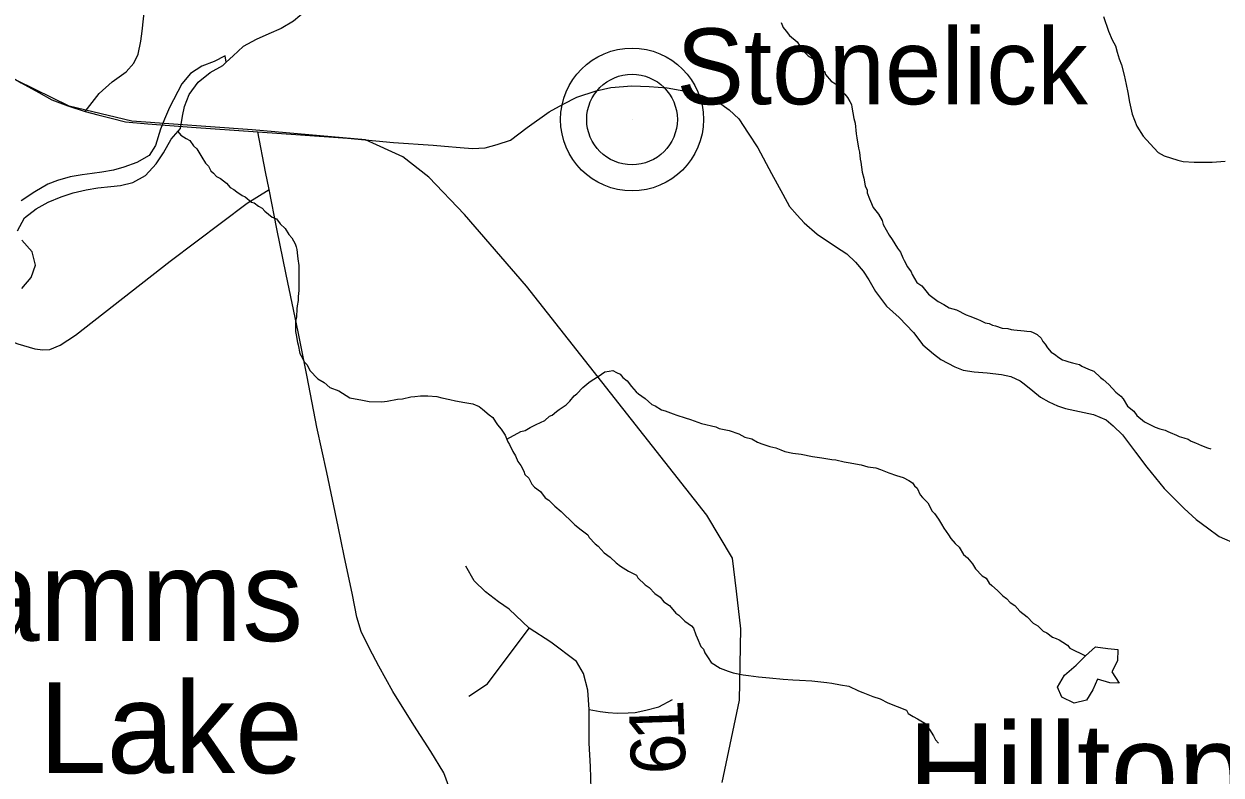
# Model space of a CAD drawing. Extents: x 0 to 34, y 0 to 22.
# Drawn here: x 4.243 to 5.489, y 19.569 to 20.352 of the extents above; entities that cross this region are included whole.
import ezdxf

# ---------------------------------------------------------------- set-up
doc = ezdxf.new("R2010")
doc.units = 0
for name, color, linetype in [('GM_X_County_Road', 7, 'Continuous'), ('GM_X_Major_River', 7, 'Continuous'), ('GM_X_Minor_Lake', 7, 'Continuous'), ('GM_X_Minor_Lake_Text', 7, 'Continuous'), ('GM_X_Minor_River', 7, 'Continuous'), ('GM_X_Rail_Line', 7, 'Continuous'), ('GM_X_State_Route', 7, 'Continuous'), ('GM_X_Township_Road', 7, 'Continuous'), ('GM_X_Township_Road_Text', 7, 'Continuous'), ('GM_X_Unincorporated', 7, 'Continuous'), ('GM_X_Unincorporated_Location', 7, 'Continuous'), ('GM_X_Unincorporated_Text', 7, 'Continuous'), ('GM_X_US_Route', 7, 'Continuous')]:
    doc.layers.add(name, color=color, linetype=linetype)

msp = doc.modelspace()

# ---------------------------------------------------------------- linework, layer by layer
at = {"layer": 'GM_X_County_Road'}
for points in [[(4.3064, 20.2608), (4.321, 20.2794), (4.3346, 20.2916), (4.3491, 20.3021), (4.3573, 20.3109), (4.3617, 20.3202), (4.3643, 20.3339), (4.3659, 20.3445), (4.3681, 20.367)], [(3.9526, 20.0204), (3.9769, 20.0241), (4.0253, 20.0318), (4.079, 20.0398), (4.14, 20.0481), (4.1548, 20.0481), (4.1672, 20.0451), (4.1845, 20.0388), (4.2363, 20.0188), (4.254, 20.0134), (4.2623, 20.0125), (4.2697, 20.0128), (4.2806, 20.0172), (4.2963, 20.0276), (4.3951, 20.1048), (4.4752, 20.1652), (4.4982, 20.1794)]]:
    msp.add_lwpolyline(points, dxfattribs=at)
at = {"layer": 'GM_X_Major_River'}
for points in [[(4.5679, 20.3824), (4.5488, 20.3747), (4.5365, 20.3658), (4.5234, 20.3546), (4.5104, 20.3472), (4.4977, 20.3417), (4.4847, 20.3355), (4.4709, 20.3285), (4.4605, 20.3188), (4.4533, 20.312)], [(4.4533, 20.312), (4.4522, 20.3185), (4.4407, 20.3126), (4.4281, 20.3079), (4.4162, 20.3001), (4.4073, 20.2896), (4.3943, 20.2647), (4.3892, 20.2527), (4.3848, 20.2421), (4.3796, 20.2251), (4.373, 20.2149), (4.3603, 20.2075), (4.3466, 20.2028), (4.3359, 20.1996), (4.3237, 20.1975), (4.3138, 20.1961), (4.3035, 20.1948), (4.291, 20.1927), (4.2776, 20.1887), (4.2677, 20.1851), (4.2539, 20.177), (4.24, 20.1677)], [(4.2361, 20.1362), (4.2432, 20.1498), (4.2555, 20.1591), (4.2681, 20.1661), (4.2815, 20.1719), (4.2941, 20.1759), (4.3075, 20.1791), (4.3196, 20.1812), (4.3333, 20.1825), (4.3432, 20.1835), (4.3562, 20.1867), (4.3692, 20.1941), (4.3804, 20.206), (4.3882, 20.2177), (4.3961, 20.232), (4.4057, 20.2429), (4.4078, 20.2558), (4.4099, 20.266), (4.4147, 20.2785), (4.424, 20.2912), (4.4367, 20.3013), (4.4497, 20.3087), (4.4533, 20.312)], [(4.2404, 20.0761), (4.2501, 20.0877), (4.2549, 20.1005), (4.2513, 20.1143), (4.2405, 20.1266)]]:
    msp.add_lwpolyline(points, dxfattribs=at)
at = {"layer": 'GM_X_Minor_Lake'}
msp.add_lwpolyline([(5.3481, 19.6936), (5.3585, 19.7029), (5.3714, 19.7012), (5.3817, 19.7002), (5.3815, 19.6884), (5.3756, 19.6771), (5.383, 19.6652), (5.3735, 19.6654), (5.3606, 19.6694), (5.3558, 19.6581), (5.3492, 19.6476), (5.3362, 19.6444), (5.3234, 19.6507), (5.319, 19.661), (5.3261, 19.6734), (5.3384, 19.6839)], dxfattribs=at)
at = {"layer": 'GM_X_Minor_River'}
for points in [[(5.3669, 20.3595), (5.372, 20.3442), (5.376, 20.3354), (5.3794, 20.3292), (5.3811, 20.3224), (5.3833, 20.3155), (5.3855, 20.3093), (5.3883, 20.2986), (5.3905, 20.2887), (5.3922, 20.2803), (5.3939, 20.2704), (5.3968, 20.2578), (5.4015, 20.2452), (5.4082, 20.2348), (5.4153, 20.227), (5.4239, 20.2178), (5.4299, 20.2146), (5.4442, 20.2098), (5.4499, 20.2086), (5.4613, 20.208), (5.4735, 20.2078), (5.48, 20.208), (5.4937, 20.2089)], [(5.0312, 20.3534), (5.0333, 20.3482), (5.0363, 20.3444), (5.04, 20.3398), (5.0479, 20.3332), (5.0509, 20.3285), (5.0535, 20.3247), (5.0594, 20.3185), (5.0651, 20.315), (5.0658, 20.3123), (5.0714, 20.3061), (5.0767, 20.3018), (5.0774, 20.2992), (5.0833, 20.2922), (5.0878, 20.2895), (5.0923, 20.2837), (5.0975, 20.2787), (5.1002, 20.2752), (5.1027, 20.271), (5.1046, 20.2679), (5.1049, 20.2652), (5.107, 20.2534), (5.1081, 20.2484), (5.1094, 20.2374), (5.1101, 20.2332), (5.1118, 20.2225), (5.1129, 20.2183), (5.1135, 20.211), (5.1142, 20.208), (5.1156, 20.1973), (5.1174, 20.1912), (5.1187, 20.1832), (5.1206, 20.1786), (5.1209, 20.1759), (5.1231, 20.1698), (5.1242, 20.1671), (5.1271, 20.1606), (5.1327, 20.1537), (5.1364, 20.1471), (5.1375, 20.1429), (5.1437, 20.1318), (5.1467, 20.1272), (5.1522, 20.1183), (5.1556, 20.1141), (5.1578, 20.1083), (5.1593, 20.1053), (5.1626, 20.0987), (5.1667, 20.0937), (5.1677, 20.0907), (5.1726, 20.0826), (5.1778, 20.0791), (5.1845, 20.0702), (5.1879, 20.0679), (5.1947, 20.0628), (5.2007, 20.0596), (5.2063, 20.0561), (5.2139, 20.0541), (5.2237, 20.049), (5.2278, 20.0474), (5.2358, 20.0442), (5.2388, 20.043), (5.2437, 20.0406), (5.2479, 20.0398), (5.2513, 20.0382), (5.2543, 20.0374), (5.2615, 20.035), (5.2672, 20.0345), (5.2706, 20.0337), (5.2736, 20.0333), (5.2842, 20.0323), (5.2869, 20.0319), (5.2911, 20.0314), (5.2937, 20.0306), (5.2979, 20.0283), (5.302, 20.0244), (5.3038, 20.0209), (5.306, 20.0182), (5.3086, 20.0144), (5.3124, 20.0101), (5.3158, 20.0078), (5.3203, 20.0043), (5.324, 20.0019), (5.3267, 20.0011), (5.3308, 19.9999), (5.3346, 19.9987), (5.3388, 19.9979), (5.3418, 19.9971), (5.3444, 19.9955), (5.3512, 19.9923), (5.3569, 19.99), (5.3636, 19.9834), (5.3666, 19.9814), (5.3723, 19.9764), (5.3797, 19.9683), (5.385, 19.964), (5.3872, 19.9613), (5.392, 19.9536), (5.3984, 19.9485), (5.4017, 19.9439), (5.4096, 19.9373), (5.4145, 19.9349)], [(4.403, 20.2398), (4.4061, 20.236), (4.4117, 20.2325), (4.4155, 20.2305), (4.4192, 20.2248), (4.4229, 20.2217), (4.4281, 20.2132), (4.4318, 20.2067), (4.4348, 20.2036), (4.4374, 20.199), (4.44, 20.1963), (4.4434, 20.1931), (4.4475, 20.1908), (4.4535, 20.1861), (4.4576, 20.1815), (4.4614, 20.1795), (4.4644, 20.1768), (4.47, 20.1733), (4.473, 20.1717), (4.4798, 20.1663), (4.4824, 20.1655), (4.4869, 20.162), (4.4907, 20.16), (4.4937, 20.1569), (4.5012, 20.1507), (4.5057, 20.1487), (4.5094, 20.1437), (4.5147, 20.1386), (4.5187, 20.1325), (4.5217, 20.129), (4.525, 20.1229), (4.5261, 20.1198), (4.5268, 20.1168), (4.5275, 20.1103), (4.5278, 20.1072), (4.5288, 20.1004), (4.5288, 20.0973), (4.529, 20.0886), (4.5288, 20.0741), (4.5283, 20.068), (4.5282, 20.0639), (4.5274, 20.0582), (4.5269, 20.0551), (4.5264, 20.0468), (4.5256, 20.0418), (4.5254, 20.0316), (4.5261, 20.0281), (4.5275, 20.0201), (4.5282, 20.0175), (4.53, 20.0087), (4.5314, 20.006), (4.5347, 19.9995), (4.5377, 19.9967), (4.5403, 19.991), (4.5489, 19.9821), (4.5553, 19.9782), (4.5613, 19.9731), (4.5707, 19.9695), (4.582, 19.9625), (4.5953, 19.96), (4.6021, 19.9587), (4.6154, 19.9581), (4.6211, 19.9588), (4.6318, 19.9609), (4.6368, 19.9615), (4.6455, 19.9633), (4.6497, 19.9636), (4.6558, 19.9646), (4.6634, 19.9645), (4.6725, 19.9636), (4.6778, 19.9623), (4.6862, 19.9607), (4.6922, 19.9594), (4.7017, 19.9574), (4.71, 19.9561), (4.7168, 19.9533), (4.7202, 19.9506), (4.727, 19.9447), (4.7311, 19.942), (4.7337, 19.9374), (4.7359, 19.9343), (4.7396, 19.9297), (4.7437, 19.9235), (4.7466, 19.9166), (4.7485, 19.9139), (4.7518, 19.9063), (4.7547, 19.902), (4.7569, 19.8959), (4.7603, 19.892), (4.7632, 19.8859), (4.7643, 19.8825), (4.7684, 19.8786), (4.7717, 19.8724), (4.7743, 19.8694), (4.7807, 19.8647), (4.7856, 19.8581), (4.7893, 19.8558), (4.7957, 19.8496), (4.802, 19.8441), (4.8054, 19.8407), (4.8121, 19.8341)], [(4.7454, 19.9194), (4.7601, 19.9274), (4.7647, 19.9285), (4.7697, 19.9314), (4.7762, 19.9347), (4.785, 19.9388), (4.79, 19.9432), (4.7927, 19.9443), (4.7973, 19.9481), (4.8, 19.9503), (4.8073, 19.9551), (4.8112, 19.9589), (4.8155, 19.9645), (4.8186, 19.9667), (4.8247, 19.9731), (4.8309, 19.9783), (4.8344, 19.9809), (4.8405, 19.9846), (4.8475, 19.9894), (4.852, 19.9901), (4.8558, 19.9908), (4.8596, 19.9888), (4.8634, 19.9872), (4.8664, 19.9834), (4.8709, 19.9802), (4.8753, 19.9741), (4.8802, 19.9687), (4.8828, 19.9667), (4.8896, 19.9617), (4.8967, 19.9554), (4.9001, 19.9539), (4.9065, 19.95), (4.9103, 19.9487), (4.9186, 19.9456), (4.9224, 19.9443), (4.9314, 19.9415), (4.9367, 19.9399), (4.9481, 19.9355), (4.9632, 19.9322), (4.9666, 19.9303), (4.9772, 19.9282), (4.987, 19.925), (4.9934, 19.9214), (5.0006, 19.9198), (5.0067, 19.9162), (5.0112, 19.9146), (5.0195, 19.9118), (5.0256, 19.9102), (5.0309, 19.9082), (5.035, 19.9066), (5.0433, 19.9049), (5.0521, 19.9037), (5.0638, 19.9012), (5.0737, 19.8998), (5.0839, 19.8981), (5.0881, 19.8977), (5.0968, 19.8956), (5.1032, 19.8948), (5.1085, 19.8935), (5.1146, 19.8927), (5.1214, 19.8906), (5.1244, 19.8902), (5.1298, 19.8894), (5.1347, 19.8877), (5.14, 19.8857), (5.1434, 19.8842), (5.1513, 19.8814), (5.1581, 19.8793), (5.1641, 19.8762), (5.1679, 19.8738), (5.1701, 19.8708), (5.1727, 19.8684), (5.176, 19.8615), (5.1783, 19.8584), (5.1839, 19.853), (5.1883, 19.8442), (5.1909, 19.8419), (5.195, 19.8361), (5.1983, 19.8307), (5.2005, 19.8265), (5.2054, 19.8196), (5.208, 19.8157), (5.2124, 19.8107), (5.2166, 19.8068), (5.221, 19.7991), (5.2251, 19.7956), (5.2303, 19.7894), (5.2337, 19.7841), (5.2404, 19.7771), (5.2445, 19.7744), (5.2479, 19.7694), (5.2505, 19.767), (5.2565, 19.7616), (5.2621, 19.7562), (5.2658, 19.7534), (5.2696, 19.7492), (5.2745, 19.7461), (5.2797, 19.7403), (5.2872, 19.7344), (5.2935, 19.7275), (5.2984, 19.7247)], [(5.4145, 19.9349), (5.4205, 19.9318), (5.4255, 19.9302), (5.4311, 19.9286), (5.4338, 19.9274), (5.4364, 19.9262), (5.4428, 19.9234), (5.4455, 19.9222), (5.4504, 19.9206), (5.4549, 19.9194), (5.4583, 19.9174), (5.4628, 19.9154), (5.4689, 19.9127), (5.4753, 19.9103), (5.4787, 19.9091)], [(4.8121, 19.8341), (4.8163, 19.8302), (4.823, 19.8248), (4.8298, 19.8197), (4.8312, 19.817), (4.8376, 19.8104), (4.8406, 19.8077), (4.8469, 19.8008), (4.8533, 19.7965), (4.8593, 19.7906), (4.8638, 19.7871), (4.8721, 19.7817), (4.8804, 19.7777), (4.8819, 19.775), (4.8897, 19.7677), (4.8939, 19.7649), (4.8998, 19.7587), (4.9051, 19.7548), (4.9092, 19.7498), (4.9148, 19.7459), (4.9215, 19.7382), (4.9245, 19.7359), (4.9309, 19.7297), (4.9377, 19.725), (4.9399, 19.7223), (4.9424, 19.7154), (4.9439, 19.7123), (4.9476, 19.7035), (4.9502, 19.7004), (4.9516, 19.6966), (4.9553, 19.6916), (4.9583, 19.6866), (4.9677, 19.6807), (4.976, 19.6775), (4.9813, 19.6759), (4.9915, 19.6738), (4.9972, 19.673), (5.0075, 19.6717), (5.0192, 19.6707), (5.0333, 19.6693), (5.0435, 19.6687), (5.0504, 19.6682), (5.0633, 19.6676), (5.0788, 19.6658), (5.0838, 19.665), (5.0929, 19.6633), (5.1016, 19.662), (5.1118, 19.6573), (5.1163, 19.6553), (5.1265, 19.6513), (5.1344, 19.6489), (5.1424, 19.6446), (5.1616, 19.637), (5.1635, 19.6335), (5.1687, 19.6304), (5.1732, 19.628), (5.18, 19.6237), (5.1837, 19.6195), (5.1856, 19.6168), (5.1897, 19.6103), (5.1919, 19.606), (5.1949, 19.6026)], [(5.2984, 19.7247), (5.304, 19.7193), (5.3078, 19.7177), (5.3138, 19.713), (5.3176, 19.7118), (5.3206, 19.7103), (5.3244, 19.7079), (5.3293, 19.7048), (5.3319, 19.7017), (5.3481, 19.6936)], [(5.3384, 19.6839), (5.3481, 19.6936)]]:
    msp.add_lwpolyline(points, dxfattribs=at)
at = {"layer": 'GM_X_Rail_Line'}
msp.add_lwpolyline([(4.9699, 19.5616), (4.9877, 19.6476), (4.9893, 19.7216), (4.9846, 19.761), (4.9805, 19.7952), (4.9538, 19.8401), (4.766, 20.0788), (4.7015, 20.1533), (4.6644, 20.1922), (4.6371, 20.2133), (4.5984, 20.231), (4.4805, 20.2416), (4.355, 20.2505), (4.2898, 20.2661), (4.2359, 20.2925)], dxfattribs=at)
at = {"layer": 'GM_X_State_Route'}
msp.add_lwpolyline([(4.6862, 19.5547), (4.68, 19.5717), (4.6663, 19.5939), (4.6486, 19.6215), (4.6267, 19.6563), (4.6121, 19.683), (4.6024, 19.7011), (4.5939, 19.7191), (4.5894, 19.734), (4.5847, 19.7572), (4.576, 19.7979), (4.57, 19.8285), (4.558, 19.8847), (4.5478, 19.9318), (4.5376, 19.9842), (4.5283, 20.0311), (4.5159, 20.0907), (4.5062, 20.1383), (4.4982, 20.1794), (4.4944, 20.1979), (4.4863, 20.2393)], dxfattribs=at)
at = {"layer": 'GM_X_Township_Road'}
for points in [[(4.7954, 19.432), (4.8026, 19.4606), (4.8026, 19.4813), (4.806, 19.4979), (4.814, 19.5166), (4.8246, 19.5346), (4.8333, 19.5546), (4.8326, 19.5785), (4.8313, 19.6025), (4.8313, 19.6265), (4.8313, 19.6378), (4.83, 19.6578), (4.8253, 19.6751), (4.818, 19.6878), (4.7913, 19.7078), (4.7687, 19.7224), (4.748, 19.7424), (4.7367, 19.7497), (4.7234, 19.7604), (4.7114, 19.7717), (4.7027, 19.787)], [(4.7061, 19.6517), (4.7255, 19.6645), (4.7687, 19.7224)], [(4.8313, 19.6378), (4.8428, 19.6357), (4.8512, 19.6346), (4.8605, 19.6339), (4.8718, 19.6342), (4.8791, 19.6347), (4.8904, 19.637), (4.9038, 19.6405), (4.918, 19.648)]]:
    msp.add_lwpolyline(points, dxfattribs=at)
at = {"layer": 'GM_X_Unincorporated'}
for radius in [0.0744, 0.0472]:
    msp.add_circle((4.8759, 20.2523), radius, dxfattribs=at)
at = {"layer": 'GM_X_Unincorporated_Location'}
msp.add_line((4.8759, 20.2523), (4.8759, 20.2523), dxfattribs=at)
at = {"layer": 'GM_X_US_Route'}
for points in [[(4.1775, 20.335), (4.196, 20.32), (4.2223, 20.3008), (4.2398, 20.2905), (4.2581, 20.2806), (4.2717, 20.2729), (4.2883, 20.2667), (4.3064, 20.2608)], [(4.3064, 20.2608), (4.3198, 20.2572), (4.3337, 20.2538), (4.3486, 20.25), (4.3717, 20.2479), (4.4173, 20.2445), (4.4863, 20.2393), (4.5307, 20.2364), (4.5796, 20.2329), (4.6275, 20.2283), (4.6688, 20.2256), (4.6805, 20.2247), (4.6969, 20.2232), (4.7098, 20.2221), (4.723, 20.2229), (4.7356, 20.2264), (4.7493, 20.2309), (4.7667, 20.244), (4.7895, 20.2602), (4.8041, 20.2682), (4.8183, 20.2755), (4.8385, 20.2821), (4.8537, 20.2858), (4.8757, 20.2875), (4.8938, 20.2868), (4.9124, 20.2853), (4.9338, 20.2815), (4.9491, 20.2774), (4.966, 20.2702), (4.9769, 20.2623), (4.9871, 20.2529), (4.9968, 20.2381), (5.0068, 20.2227), (5.0213, 20.1961), (5.033, 20.1747), (5.04, 20.1618), (5.0477, 20.1526), (5.055, 20.1445), (5.0686, 20.1329), (5.0877, 20.1199), (5.0995, 20.1125), (5.1087, 20.1036), (5.1165, 20.0944), (5.1225, 20.0853), (5.1294, 20.073), (5.1408, 20.0577), (5.154, 20.0462), (5.1689, 20.0304), (5.1788, 20.0176), (5.1898, 20.0081), (5.1976, 20.0024), (5.212, 19.9947), (5.2208, 19.9912), (5.2322, 19.9895), (5.2456, 19.9884), (5.2605, 19.9866), (5.2704, 19.9847), (5.2801, 19.9801), (5.2844, 19.9768), (5.2934, 19.9698), (5.3014, 19.9631), (5.3098, 19.9583), (5.3188, 19.954), (5.3274, 19.9512), (5.3564, 19.9451), (5.3697, 19.9394), (5.3769, 19.9332), (5.3866, 19.9238), (5.4001, 19.9059), (5.4118, 19.89), (5.4301, 19.868), (5.4509, 19.8472), (5.4635, 19.8358), (5.4751, 19.827), (5.4873, 19.8179), (5.5063, 19.8097)]]:
    msp.add_lwpolyline(points, dxfattribs=at)

# ---------------------------------------------------------------- texts
at = {"layer": 'GM_X_Minor_Lake_Text'}
for s, rotation, p in [('Damms', 359.9999, (4.0973, 19.7091)), ('Lake', 359.9998, (4.2585, 19.5714)), ('Hilltop', 359.9965, (5.1633, 19.5287))]:
    msp.add_text(s, height=0.09469, rotation=rotation, dxfattribs=at).set_placement(p)
at = {"layer": 'GM_X_Township_Road_Text'}
for s, rotation, p in [('1', 91.9466, (4.9306, 19.6062)), ('6', 92.8002, (4.9323, 19.5714))]:
    msp.add_text(s, height=0.0568, rotation=rotation, dxfattribs=at).set_placement(p)
at = {"layer": 'GM_X_Unincorporated_Text'}
msp.add_text('Stonelick', height=0.07898, rotation=0, dxfattribs=at).set_placement((4.922, 20.2682))

doc.saveas('drawing.dxf')
